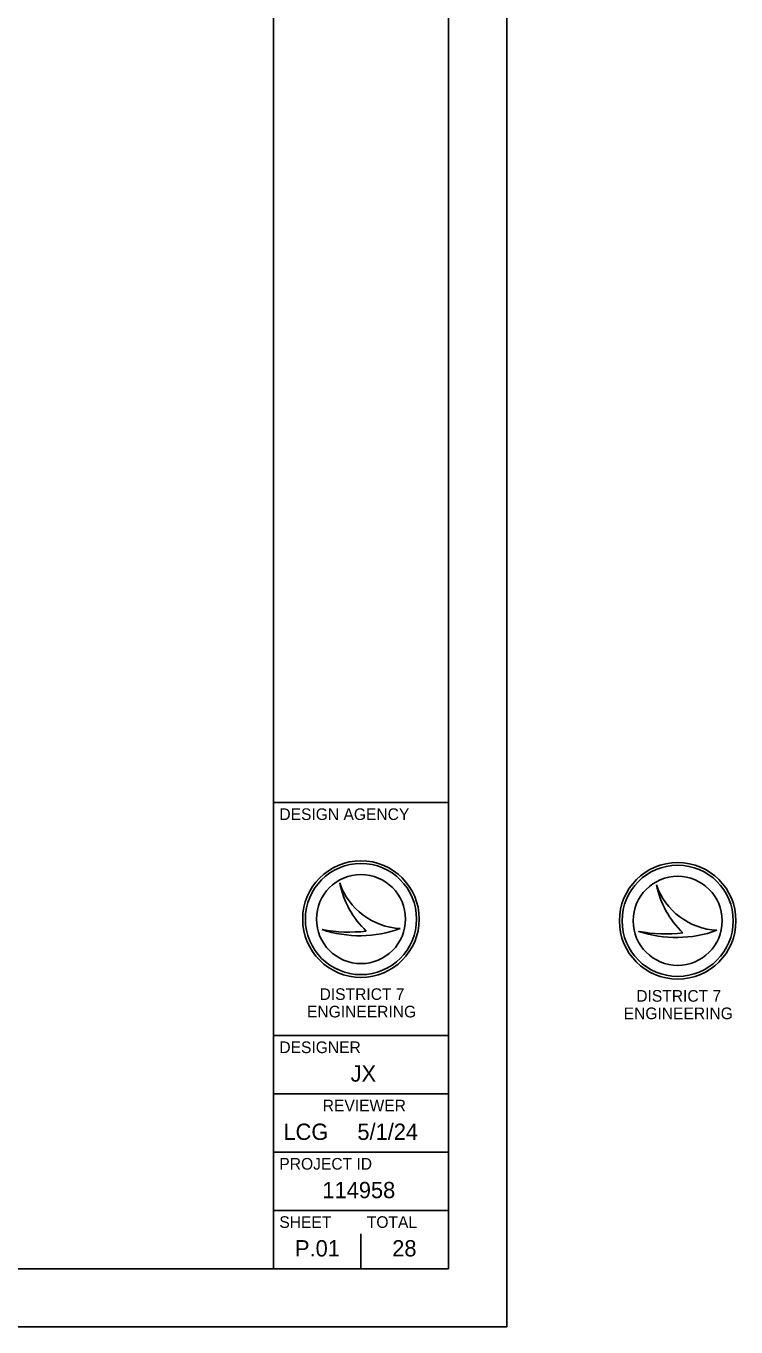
# Model space of a CAD drawing. Extents: x 0 to 36, y 0 to 22.
# Drawn here: x 29.88 to 35.97, y 0 to 11.16 of the extents above; entities that cross this region are included whole.
import ezdxf

# ---------------------------------------------------------------- set-up
doc = ezdxf.new("R2010")
doc.units = 0
for name, color, linetype in [('SH_Border', 7, 'Continuous'), ('SH_Cut_Line', 7, 'Continuous'), ('SH_Data', 7, 'Continuous'), ('SH_Text', 7, 'Continuous')]:
    doc.layers.add(name, color=color, linetype=linetype)

msp = doc.modelspace()

# ---------------------------------------------------------------- linework, layer by layer
at = {"layer": 'SH_Border'}
for p, q in [((32, 0.5), (32, 21.5)), ((32, 4.5), (33.5, 4.5)), ((32, 2.5), (33.5, 2.5)), ((32, 2), (33.5, 2)), ((32, 1.5), (33.5, 1.5)), ((32, 1), (33.5, 1))]:
    msp.add_line(p, q, dxfattribs=at)
msp.add_lwpolyline([(1.5, 21.5), (33.5, 21.5), (33.5, 0.5), (1.5, 0.5)], close=True, dxfattribs=at)
at = {"layer": 'SH_Cut_Line'}
msp.add_lwpolyline([(0, 0), (34, 0), (34, 22), (0, 22)], close=True, dxfattribs=at)
at = {"layer": 'SH_Data'}
for p, q in [((32.567, 3.81), (32.567, 3.81)), ((35.283, 3.795), (35.283, 3.795)), ((32.75, 3.5), (32.75, 3.5)), ((32.417, 3.41), (32.417, 3.41)), ((33.087, 3.419), (33.087, 3.419)), ((35.133, 3.394), (35.133, 3.395)), ((35.803, 3.403), (35.803, 3.403)), ((32.75, 0.5), (32.75, 0.8)), ((32.375, 0.675), (32.375, 0.675))]:
    msp.add_line(p, q, dxfattribs=at)
for centre, radius in [((32.75, 3.5), 0.5), ((32.75, 3.5), 0.477), ((32.75, 3.5), 0.477), ((35.466, 3.485), 0.5), ((35.466, 3.485), 0.477), ((35.466, 3.485), 0.477), ((32.75, 3.5), 0.382), ((35.466, 3.485), 0.382)]:
    msp.add_circle(centre, radius, dxfattribs=at)
for centre, radius, start, end in [((33.116, 3.998), 0.58, 198.9257, 198.9319), ((33.347, 3.97), 0.796, 191.6379, 191.6421), ((33.116, 3.998), 0.58, 198.9319, 267.1657), ((33.347, 3.97), 0.796, 191.6421, 226.0947), ((35.832, 3.983), 0.58, 198.9257, 198.9319), ((36.063, 3.955), 0.796, 191.6379, 191.6421), ((35.832, 3.983), 0.58, 198.9319, 267.1657), ((36.063, 3.955), 0.796, 191.6421, 226.0947), ((32.739, 4.37), 1.013, 251.4576, 290.0832), ((32.648, 4.654), 1.266, 259.4964, 259.4995), ((32.739, 4.37), 1.013, 251.4527, 251.4576), ((32.648, 4.654), 1.266, 259.4995, 276.6672), ((35.455, 4.355), 1.013, 251.4576, 290.0832), ((35.455, 4.355), 1.013, 251.4527, 251.4576), ((35.364, 4.639), 1.266, 259.4964, 259.4995), ((35.364, 4.639), 1.266, 259.4995, 276.6672)]:
    msp.add_arc(centre, radius, start, end, dxfattribs=at)

# ---------------------------------------------------------------- texts
for s, height, p in [('DESIGN AGENCY', 0.1, (32.05, 4.35)), ('DESIGNER', 0.1, (32.05, 2.35)), ('JX', 0.14, (32.661, 2.105)), ('REVIEWER', 0.1, (32.422, 1.85)), ('LCG', 0.14, (32.085, 1.605)), ('5/1/24', 0.14, (32.719, 1.605)), ('PROJECT ID', 0.1, (32.05, 1.35)), ('114958', 0.14, (32.419, 1.105)), ('SHEET', 0.1, (32.05, 0.85)), ('TOTAL', 0.1, (32.8, 0.85)), ('P.01', 0.14, (32.184, 0.605)), ('28', 0.14, (33.018, 0.605))]:
    msp.add_text(s, height=height, dxfattribs=at).set_placement(p)
at = {"layer": 'SH_Text'}
for s, p in [('DISTRICT 7', (32.395, 2.806)), ('DISTRICT 7', (35.111, 2.791)), ('ENGINEERING', (32.287, 2.656)), ('ENGINEERING', (35.003, 2.641))]:
    msp.add_text(s, height=0.1, dxfattribs=at).set_placement(p)

doc.saveas('drawing.dxf')
